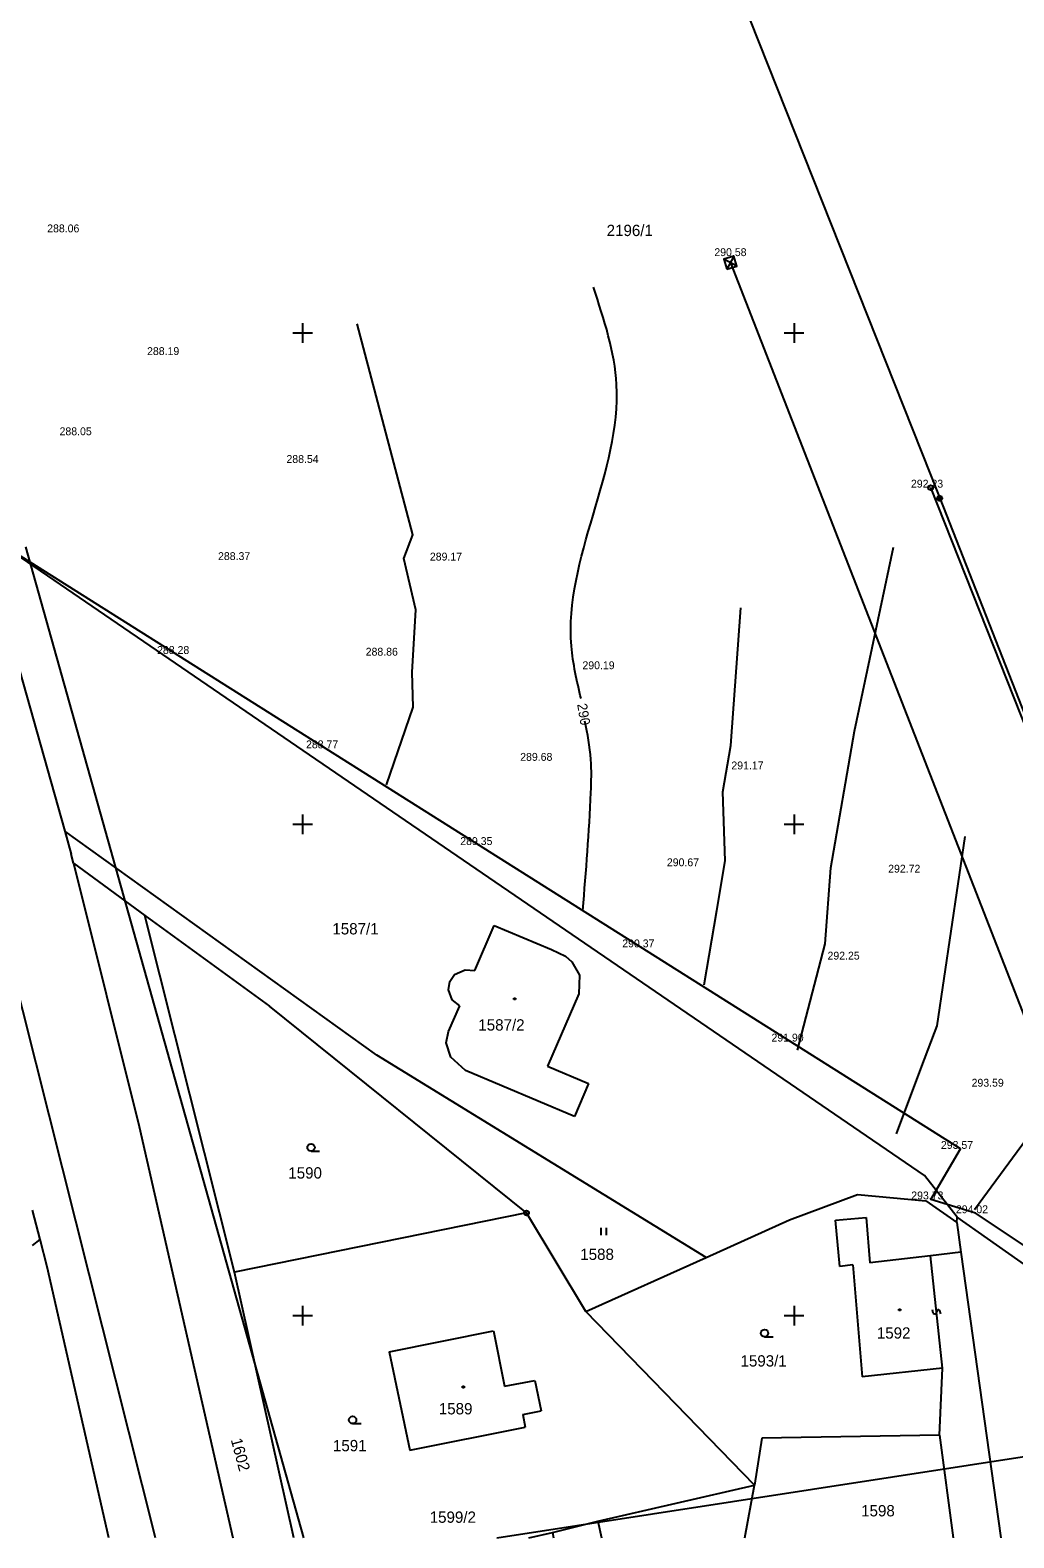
# Model space of a CAD drawing. Extents: x -504375 to -503125, y -1118000 to -1116474.
# Drawn here: x -504027.7 to -503927.6, y -1117672.6 to -1117519.2 of the extents above; entities that cross this region are included whole.
import ezdxf

# ---------------------------------------------------------------- set-up
doc = ezdxf.new("R2010")
doc.units = 0
for name, color, linetype in [('Elektro', 7, 'Continuous'), ('Ploty', 7, 'Continuous'), ('Podkladové mapy', 7, 'Continuous'), ('Vrstva 34', 7, 'Continuous'), ('Vrstva 48', 7, 'Continuous'), ('Výšky bodů plotr', 7, 'Continuous')]:
    doc.layers.add(name, color=color, linetype=linetype)

msp = doc.modelspace()

# ---------------------------------------------------------------- linework, layer by layer
at = {"layer": 'Elektro'}
msp.add_lwpolyline([(-503956.83, -1117543.5), (-503955.83, -1117543.2), (-503956.137, -1117542.178), (-503957.137, -1117542.478)], close=True, dxfattribs=at)
for points in [[(-503956.137, -1117542.178), (-503956.83, -1117543.5)], [(-503955.83, -1117543.2), (-503957.137, -1117542.478)], [(-503956.484, -1117542.839), (-503911.458, -1117658.334)], [(-503936.11, -1117565.73), (-503894.299, -1117671.279)]]:
    msp.add_lwpolyline(points, dxfattribs=at)
msp.add_circle((-503936.11, -1117565.73), 0.25, dxfattribs=at)
at = {"layer": 'Ploty'}
msp.add_lwpolyline([(-503918.907, -1117667.255), (-503907.07, -1117658.18), (-503922.82, -1117645.38), (-503931.54, -1117639.57), (-503936.08, -1117638.16), (-503933.06, -1117633.02), (-504033.06, -1117569.97), (-504030.05, -1117581.29)], dxfattribs=at)
at = {"layer": 'Podkladové mapy'}
for p, q in [((-503984.514, -1117442.374), (-503935.19, -1117566.81)), ((-503935.44, -1117566.76), (-503935.39, -1117566.66)), ((-503935.44, -1117566.86), (-503935.44, -1117566.76)), ((-503935.39, -1117566.96), (-503935.44, -1117566.86)), ((-503935.39, -1117566.66), (-503935.34, -1117566.61)), ((-503935.34, -1117566.61), (-503935.24, -1117566.56)), ((-503935.34, -1117566.71), (-503935.34, -1117566.91)), ((-503935.34, -1117566.91), (-503935.24, -1117566.96)), ((-503935.24, -1117566.56), (-503935.14, -1117566.56)), ((-503935.24, -1117566.96), (-503935.24, -1117566.66)), ((-503935.24, -1117566.66), (-503935.14, -1117566.66)), ((-503935.19, -1117566.81), (-503893.75, -1117672.579)), ((-503935.14, -1117566.56), (-503935.04, -1117566.61)), ((-503935.14, -1117566.66), (-503935.14, -1117566.96)), ((-503935.14, -1117566.96), (-503935.04, -1117566.91)), ((-503935.04, -1117566.61), (-503934.99, -1117566.66)), ((-503935.04, -1117566.91), (-503935.04, -1117566.71)), ((-503934.99, -1117566.66), (-503934.94, -1117566.76)), ((-503934.94, -1117566.86), (-503934.99, -1117566.96)), ((-503934.94, -1117566.76), (-503934.94, -1117566.86)), ((-503936.73, -1117635.73), (-504035.1, -1117568.44)), ((-503935.34, -1117567.01), (-503935.39, -1117566.96)), ((-503935.24, -1117567.06), (-503935.34, -1117567.01)), ((-503935.14, -1117567.06), (-503935.24, -1117567.06)), ((-503935.04, -1117567.01), (-503935.14, -1117567.06)), ((-503934.99, -1117566.96), (-503935.04, -1117567.01)), ((-504028.19, -1117571.77), (-503999.914, -1117672.599)), ((-504030.57, -1117578.05), (-504024.19, -1117600.69)), ((-504024.19, -1117600.69), (-504023.53, -1117603.04)), ((-503992.43, -1117623.48), (-504024.19, -1117600.69)), ((-504023.32, -1117603.95), (-504023.53, -1117603.04)), ((-504023.32, -1117603.95), (-504016.64, -1117630.75)), ((-504023.32, -1117603.95), (-504016.03, -1117609.26)), ((-504014.953, -1117672.602), (-504031.58, -1117606.58)), ((-504006.92, -1117645.57), (-504016.03, -1117609.26)), ((-504016.03, -1117609.26), (-504003.36, -1117618.49)), ((-503982.47, -1117614.86), (-503980.51, -1117610.28)), ((-503980.51, -1117610.28), (-503974.68, -1117612.73)), ((-503974.68, -1117612.73), (-503973.26, -1117613.42)), ((-503973.26, -1117613.42), (-503972.61, -1117613.99)), ((-503972.61, -1117613.99), (-503971.84, -1117615.33)), ((-503985.17, -1117616.83), (-503985.01, -1117615.99)), ((-503985.01, -1117615.99), (-503984.54, -1117615.29)), ((-503984.54, -1117615.29), (-503983.47, -1117614.79)), ((-503983.47, -1117614.79), (-503982.47, -1117614.86)), ((-503971.84, -1117615.33), (-503971.9, -1117617.24)), ((-503984.77, -1117617.85), (-503985.17, -1117616.83)), ((-503971.9, -1117617.24), (-503975.1, -1117624.6)), ((-503977.22, -1117639.54), (-504003.36, -1117618.49)), ((-503985.16, -1117621.08), (-503984.01, -1117618.45)), ((-503984.01, -1117618.45), (-503984.77, -1117617.85)), ((-503978.5, -1117617.68), (-503978.35, -1117617.68)), ((-503978.5, -1117617.83), (-503978.5, -1117617.68)), ((-503978.35, -1117617.83), (-503978.5, -1117617.83)), ((-503978.35, -1117617.68), (-503978.35, -1117617.83)), ((-503985.38, -1117622.23), (-503985.16, -1117621.08)), ((-503958.95, -1117644.06), (-503992.43, -1117623.48)), ((-503984.93, -1117623.7), (-503985.38, -1117622.23)), ((-503983.42, -1117625.04), (-503984.93, -1117623.7)), ((-503972.34, -1117629.72), (-503983.42, -1117625.04)), ((-503975.1, -1117624.6), (-503970.93, -1117626.38)), ((-503970.93, -1117626.38), (-503972.34, -1117629.72)), ((-504016.64, -1117630.75), (-504007.089, -1117672.6)), ((-503999.14, -1117633.25), (-503998.265, -1117633.25)), ((-503933.4, -1117639.97), (-503936.73, -1117635.73)), ((-503950.46, -1117640.23), (-503943.55, -1117637.67)), ((-503943.55, -1117637.67), (-503936.6, -1117638.31)), ((-503936.6, -1117638.31), (-503933.46, -1117640.5)), ((-504026.7, -1117642.25), (-504027.484, -1117639.273)), ((-503977.22, -1117639.54), (-504006.92, -1117645.57)), ((-503971.17, -1117649.57), (-503977.22, -1117639.54)), ((-503958.95, -1117644.06), (-503950.46, -1117640.23)), ((-503945.79, -1117640.27), (-503942.67, -1117640.01)), ((-503945.36, -1117644.98), (-503945.79, -1117640.27)), ((-503942.67, -1117640.01), (-503942.3, -1117644.62)), ((-503933.46, -1117640.5), (-503933.4, -1117639.97)), ((-503933.46, -1117640.5), (-503933.04, -1117643.53)), ((-503907.01, -1117658.6), (-503933.4, -1117639.97)), ((-503969.61, -1117641.79), (-503969.61, -1117641.04)), ((-503969.11, -1117641.04), (-503969.11, -1117641.79)), ((-504027.484, -1117642.838), (-504026.7, -1117642.25)), ((-504025.99, -1117645.01), (-504026.7, -1117642.25)), ((-503933.04, -1117643.53), (-503936.11, -1117643.89)), ((-503933.04, -1117643.53), (-503928.979, -1117672.586)), ((-504019.71, -1117672.603), (-504025.99, -1117645.01)), ((-503971.17, -1117649.57), (-503958.95, -1117644.06)), ((-503944.03, -1117644.82), (-503945.36, -1117644.98)), ((-503944.03, -1117644.82), (-503943.07, -1117656.21)), ((-503936.11, -1117643.89), (-503942.3, -1117644.62)), ((-503934.89, -1117655.34), (-503936.11, -1117643.89)), ((-504000.878, -1117672.599), (-504006.92, -1117645.57)), ((-503954.04, -1117667.24), (-503971.17, -1117649.57)), ((-503939.34, -1117649.32), (-503939.19, -1117649.32)), ((-503939.34, -1117649.47), (-503939.34, -1117649.32)), ((-503939.19, -1117649.47), (-503939.34, -1117649.47)), ((-503939.19, -1117649.32), (-503939.19, -1117649.47)), ((-503935.837, -1117649.752), (-503935.924, -1117649.408)), ((-503935.727, -1117649.84), (-503935.837, -1117649.752)), ((-503935.539, -1117649.72), (-503935.628, -1117649.83)), ((-503935.46, -1117649.51), (-503935.539, -1117649.72)), ((-503935.372, -1117649.4), (-503935.46, -1117649.51)), ((-503935.272, -1117649.389), (-503935.372, -1117649.4)), ((-503935.162, -1117649.478), (-503935.272, -1117649.389)), ((-503935.075, -1117649.821), (-503935.162, -1117649.478)), ((-503935.628, -1117649.83), (-503935.727, -1117649.84)), ((-503991.2, -1117653.67), (-503980.59, -1117651.55)), ((-503980.59, -1117651.55), (-503979.47, -1117657.18)), ((-503953, -1117652.16), (-503952.125, -1117652.16)), ((-503991.2, -1117653.67), (-503989.1, -1117663.67)), ((-503934.89, -1117655.34), (-503943.07, -1117656.21)), ((-503935.2, -1117662.14), (-503934.89, -1117655.34)), ((-503983.72, -1117657.18), (-503983.57, -1117657.18)), ((-503983.72, -1117657.33), (-503983.72, -1117657.18)), ((-503983.57, -1117657.33), (-503983.72, -1117657.33)), ((-503983.57, -1117657.18), (-503983.57, -1117657.33)), ((-503979.47, -1117657.18), (-503976.39, -1117656.59)), ((-503976.39, -1117656.59), (-503975.73, -1117659.68)), ((-503980.228, -1117672.595), (-503885.92, -1117658.08)), ((-503977.59, -1117660.04), (-503975.73, -1117659.68)), ((-503977.59, -1117660.04), (-503977.34, -1117661.33)), ((-503994.91, -1117660.98), (-503994.035, -1117660.98)), ((-503989.1, -1117663.67), (-503977.34, -1117661.33)), ((-503953.27, -1117662.47), (-503954.04, -1117667.24)), ((-503935.2, -1117662.14), (-503953.27, -1117662.47)), ((-503935.2, -1117662.14), (-503933.801, -1117672.587)), ((-503969.96, -1117670.91), (-503954.04, -1117667.24)), ((-503955.02, -1117672.591), (-503954.04, -1117667.24)), ((-503974.59, -1117672.05), (-503969.96, -1117670.91)), ((-503969.96, -1117670.91), (-503969.584, -1117672.593)), ((-503976.996, -1117672.595), (-503974.59, -1117672.05)), ((-503974.59, -1117672.05), (-503974.466, -1117672.594))]:
    msp.add_line(p, q, dxfattribs=at)
for centre, radius in [((-503999.14, -1117632.875), 0.375), ((-503977.22, -1117639.54), 0.25), ((-503977.22, -1117639.54), 0.005), ((-503953, -1117651.785), 0.375), ((-503994.91, -1117660.605), 0.375)]:
    msp.add_circle(centre, radius, dxfattribs=at)
at = {"layer": 'Vrstva 34'}
for p, q in [((-503999, -1117550), (-504001, -1117550)), ((-504000, -1117549), (-504000, -1117551)), ((-503949, -1117550), (-503951, -1117550)), ((-503950, -1117549), (-503950, -1117551)), ((-504000, -1117599), (-504000, -1117601)), ((-503950, -1117599), (-503950, -1117601)), ((-503999, -1117600), (-504001, -1117600)), ((-503949, -1117600), (-503951, -1117600)), ((-504000, -1117649), (-504000, -1117651)), ((-503950, -1117649), (-503950, -1117651)), ((-503999, -1117650), (-504001, -1117650)), ((-503949, -1117650), (-503951, -1117650))]:
    msp.add_line(p, q, dxfattribs=at)
at = {"layer": 'Vrstva 48'}
for points in [[(-503991.453, -1117595.978), (-503988.736, -1117588.073), (-503988.862, -1117584.518), (-503988.485, -1117578.16), (-503989.698, -1117572.932), (-503988.778, -1117570.548), (-503994.447, -1117549.074)], [(-503949.656, -1117622.979), (-503946.824, -1117612.164), (-503946.246, -1117604.415), (-503943.85, -1117590.515), (-503939.885, -1117571.794)], [(-503959.155, -1117616.313), (-503957.875, -1117608.747), (-503957.023, -1117603.71), (-503957.235, -1117596.7), (-503956.421, -1117591.985), (-503955.432, -1117577.959)], [(-503939.598, -1117631.481), (-503936.997, -1117624.599), (-503935.444, -1117620.491), (-503932.603, -1117601.234)], [(-503931.66, -1117639.187), (-503925.125, -1117630.342), (-503922.834, -1117614.998)]]:
    msp.add_lwpolyline(points, dxfattribs=at)
for points in [[(-503971.668, -1117587.203), (-503972.651, -1117581.859), (-503968.056, -1117555.244), (-503970.418, -1117545.316)], [(-503971.487, -1117608.747), (-503970.673, -1117596.758), (-503970.673, -1117593.382), (-503971.274, -1117589.495)]]:
    msp.add_spline(points, degree=3, dxfattribs=at)

# ---------------------------------------------------------------- texts
at = {"layer": 'Podkladové mapy'}
for s, p in [('2196/1', (-503969.066, -1117540.131)), ('1587/1', (-503996.97, -1117611.2)), ('1587/2', (-503982.12, -1117620.98)), ('1590', (-504001.45, -1117636.04)), ('1588', (-503971.75, -1117644.32)), ('1592', (-503941.58, -1117652.33)), ('1593/1', (-503955.45, -1117655.17)), ('1589', (-503986.14, -1117660.04)), ('1591', (-503996.91, -1117663.79)), ('1598', (-503943.177, -1117670.42)), ('1599/2', (-503987.067, -1117671.07))]:
    msp.add_text(s, height=1.15, dxfattribs=at).set_placement(p)
msp.add_text('1602', height=1.15, rotation=284.96358, dxfattribs=at).set_placement((-504007.31, -1117662.62))
at = {"layer": 'Vrstva 48'}
msp.add_text('290', height=1, rotation=279.67765, dxfattribs=at).set_placement((-503972.076, -1117587.78))
at = {"layer": 'Výšky bodů plotr'}
for s, p in [('288.06 ', (-504025.98, -1117539.75)), ('290.58 ', (-503958.11, -1117542.17)), ('288.19 ', (-504015.82, -1117552.24)), ('288.05 ', (-504024.72, -1117560.4)), ('288.54 ', (-504001.64, -1117563.22)), ('292.23 ', (-503938.11, -1117565.73)), ('288.37 ', (-504008.6, -1117573.1)), ('289.17 ', (-503987.05, -1117573.15)), ('288.28 ', (-504014.8, -1117582.66)), ('288.86 ', (-503993.58, -1117582.83)), ('290.19 ', (-503971.53, -1117584.21)), ('288.77 ', (-503999.65, -1117592.26)), ('289.68 ', (-503977.86, -1117593.53)), ('291.17 ', (-503956.38, -1117594.4)), ('289.35 ', (-503983.96, -1117602.1)), ('290.67 ', (-503962.94, -1117604.26)), ('292.72 ', (-503940.43, -1117604.91)), ('290.37 ', (-503967.48, -1117612.51)), ('292.25 ', (-503946.6, -1117613.76)), ('291.90 ', (-503952.3, -1117622.1)), ('293.59 ', (-503931.94, -1117626.69)), ('293.57 ', (-503935.06, -1117633.02)), ('293.73 ', (-503938.08, -1117638.16)), ('294.02 ', (-503933.54, -1117639.57))]:
    msp.add_text(s, height=0.8, dxfattribs=at).set_placement(p)

doc.saveas('drawing.dxf')
